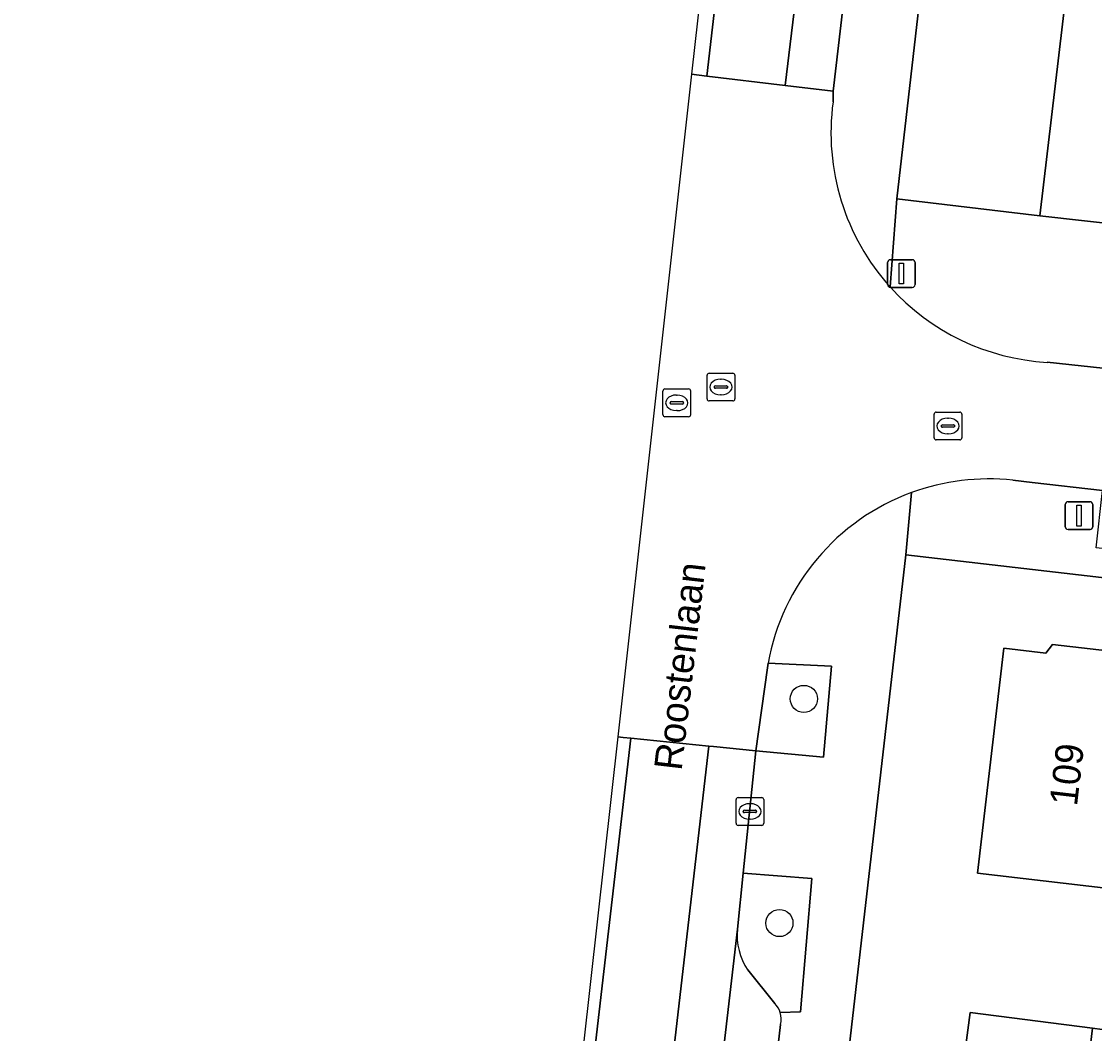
# Model space of a CAD drawing. Extents: x 162250 to 162661, y 380743 to 381606.
# Drawn here: x 162268.33 to 162306.99, y 381101.54 to 381138 of the extents above; entities that cross this region are included whole.
import ezdxf

# ---------------------------------------------------------------- set-up
doc = ezdxf.new("R2010")
doc.units = 0
for name, color, linetype in [('IMGEO_Boom', 7, 'Continuous'), ('IMGEO_Erf', 7, 'Continuous'), ('IMGEO_Kolk', 7, 'Continuous'), ('IMGEO_Lichtmast', 7, 'Continuous'), ('IMGEO_Openbare_ruimte_label', 7, 'Continuous'), ('IMGEO_Pand', 7, 'Continuous'), ('IMGEO_Pand_nummerreeks', 7, 'Continuous'), ('IMGEO_Parkeervlak_open', 7, 'Continuous'), ('IMGEO_Rijbaan_lokaal_gesloten', 7, 'Continuous'), ('IMGEO_Rioolput', 7, 'Continuous'), ('IMGEO_Verkeerseiland_groen', 7, 'Continuous'), ('IMGEO_Voetpad_open', 7, 'Continuous')]:
    doc.layers.add(name, color=color, linetype=linetype)

msp = doc.modelspace()

# ---------------------------------------------------------------- linework, layer by layer
at = {"layer": 'IMGEO_Boom'}
for centre in [(162296.514, 381113.595), (162295.634, 381105.521)]:
    msp.add_circle(centre, 0.489, dxfattribs=at)
at = {"layer": 'IMGEO_Erf'}
for points in [[(162341.565, 381113.994), (162300.19, 381118.786), (162298.069, 381100.412), (162302.196, 381099.936), (162302.502, 381102.301), (162306.912, 381101.731), (162307.261, 381101.686), (162311.531, 381101.218), (162316.15, 381100.712), (162320.788, 381100.203), (162320.754, 381099.942), (162320.583, 381098.618), (162322.993, 381098.336), (162323.098, 381101.264), (162325.575, 381101.155), (162325.478, 381098.962), (162329.957, 381098.765), (162334.625, 381098.559), (162334.521, 381096.197), (162340.767, 381095.921)], [(162312.118, 381106.22), (162307.503, 381106.762), (162302.77, 381107.317), (162303.72, 381115.418), (162305.233, 381115.24), (162305.471, 381115.559), (162308.494, 381115.204), (162311.273, 381114.878), (162311.568, 381114.505), (162313.07, 381114.329), (162317.684, 381113.787), (162322.299, 381113.246), (162326.914, 381112.705), (162328.309, 381112.541), (162328.707, 381112.855), (162331.571, 381112.519), (162334.469, 381112.179), (162334.767, 381111.802), (162336.266, 381111.626), (162335.313, 381103.499), (162330.578, 381104.055), (162325.963, 381104.596), (162321.348, 381105.137), (162316.733, 381105.679)]]:
    msp.add_lwpolyline(points, close=True, dxfattribs=at)
at = {"layer": 'IMGEO_Kolk'}
for p, q in [((162294.071, 381109.115), (162294.071, 381109.967)), ((162294.146, 381110.041), (162294.998, 381110.041)), ((162295.072, 381109.967), (162295.072, 381109.115)), ((162294.33, 381109.535), (162294.33, 381109.547)), ((162294.768, 381109.498), (162294.37, 381109.498)), ((162294.373, 381109.584), (162294.771, 381109.584)), ((162294.559, 381109.821), (162294.584, 381109.821)), ((162294.814, 381109.547), (162294.814, 381109.535)), ((162294.582, 381109.261), (162294.557, 381109.261)), ((162294.998, 381109.041), (162294.146, 381109.041))]:
    msp.add_line(p, q, dxfattribs=at)
for points in [[(162294.071, 381109.115), (162294.071, 381109.967)], [(162294.146, 381110.041), (162294.998, 381110.041)], [(162295.072, 381109.967), (162295.072, 381109.115)], [(162294.998, 381109.041), (162294.146, 381109.041)]]:
    msp.add_lwpolyline(points, dxfattribs=at)
for centre, radius, start, end in [((162294.148, 381109.965), 0.0765, 91.552, 178.448), ((162294.148, 381109.965), 0.0765, 91.552, 178.448), ((162294.996, 381109.965), 0.0765, 1.552, 88.448), ((162294.996, 381109.965), 0.0765, 1.552, 88.448), ((162294.37, 381109.544), 0.0403, 85.8775, 175.7526), ((162294.367, 381109.534), 0.0366, 178.938, 274.7102), ((162294.771, 381109.541), 0.043, 264.8664, 352.4533), ((162294.775, 381109.546), 0.0386, 1.7309, 96.639), ((162294.148, 381109.117), 0.0765, 181.552, 268.448), ((162294.148, 381109.117), 0.0765, 181.552, 268.448), ((162294.996, 381109.117), 0.0765, 271.552, 358.448), ((162294.996, 381109.117), 0.0765, 271.552, 358.448)]:
    msp.add_arc(centre, radius, start, end, dxfattribs=at)
for centre, major_axis, ratio, start_param, end_param in [((162294.558, 381109.541), (-0.387, 0.002), 0.722429, 4.712389, 7.853982), ((162294.583, 381109.541), (-0.39, 0.002), 0.717154, 1.570796, 4.712389)]:
    msp.add_ellipse(centre, major_axis=major_axis, ratio=ratio, start_param=start_param, end_param=end_param, dxfattribs=at)
at = {"layer": 'IMGEO_Lichtmast'}
for p, q in [((162299.532, 381128.517), (162299.532, 381129.317)), ((162299.532, 381129.317), (162299.532, 381128.517)), ((162299.632, 381129.417), (162300.422, 381129.417)), ((162300.422, 381129.417), (162299.632, 381129.417)), ((162300.522, 381129.317), (162300.522, 381128.517)), ((162300.522, 381128.517), (162300.522, 381129.317)), ((162300.422, 381128.417), (162299.632, 381128.417)), ((162299.632, 381128.417), (162300.422, 381128.417)), ((162306.034, 381120.698), (162306.824, 381120.698)), ((162306.824, 381120.698), (162306.034, 381120.698)), ((162305.934, 381119.798), (162305.934, 381120.598)), ((162305.934, 381120.598), (162305.934, 381119.798)), ((162306.924, 381120.598), (162306.924, 381119.798)), ((162306.924, 381119.798), (162306.924, 381120.598)), ((162306.824, 381119.698), (162306.034, 381119.698)), ((162306.034, 381119.698), (162306.824, 381119.698))]:
    msp.add_line(p, q, dxfattribs=at)
for points in [[(162299.952, 381129.292), (162300.102, 381129.292), (162300.102, 381128.542), (162299.952, 381128.542), (162299.952, 381129.292)], [(162306.354, 381120.573), (162306.504, 381120.573), (162306.504, 381119.823), (162306.354, 381119.823), (162306.354, 381120.573)]]:
    msp.add_lwpolyline(points, dxfattribs=at)
for centre, start, end in [((162299.632, 381129.317), 90, 180), ((162299.632, 381129.317), 90, 180), ((162300.422, 381129.317), 0, 90), ((162300.422, 381129.317), 360, 90), ((162299.632, 381128.517), 180, 270), ((162299.632, 381128.517), 180, 270), ((162300.422, 381128.517), 270, 0), ((162300.422, 381128.517), 270, 0), ((162306.034, 381120.598), 90, 180), ((162306.034, 381120.598), 90, 180), ((162306.824, 381120.598), 0, 90), ((162306.824, 381120.598), 360, 90), ((162306.034, 381119.798), 180, 270), ((162306.034, 381119.798), 180, 270), ((162306.824, 381119.798), 270, 0), ((162306.824, 381119.798), 270, 0)]:
    msp.add_arc(centre, 0.1, start, end, dxfattribs=at)
at = {"layer": 'IMGEO_Pand'}
for points in [[(162307.503, 381106.762), (162308.494, 381115.204), (162305.471, 381115.559), (162305.233, 381115.24), (162303.72, 381115.418), (162302.77, 381107.317)], [(162306.912, 381101.731), (162302.502, 381102.301), (162302.196, 381099.936), (162306.634, 381099.362), (162306.641, 381099.418)], [(162311.531, 381101.218), (162307.261, 381101.686), (162306.912, 381101.731), (162306.641, 381099.418), (162311.26, 381098.913), (162311.46, 381100.618), (162311.508, 381101.021)]]:
    msp.add_lwpolyline(points, close=True, dxfattribs=at)
at = {"layer": 'IMGEO_Parkeervlak_open'}
msp.add_lwpolyline([(162306.8, 381146.143), (162301.599, 381146.688), (162299.859, 381131.609), (162305.021, 381131.001)], close=True, dxfattribs=at)
for points in [[(162294.122, 381105.302), (162287.512, 381048.327)], [(162295.466, 381102.624), (162294.494, 381103.83)], [(162289.85, 381051.252), (162295.67, 381101.867)]]:
    msp.add_lwpolyline(points, dxfattribs=at)
for centre, radius, start, end in [((162296.342, 381105.08), 2.231, 174.2856, 214.0797), ((162294.924, 381102.07), 0.775, 17.0225, 45.6238), ((162294.973, 381102.074), 0.727, 343.4571, 17.8753)]:
    msp.add_arc(centre, radius, start, end, dxfattribs=at)
at = {"layer": 'IMGEO_Rijbaan_lokaal_gesloten'}
for points in [[(162292.47, 381136.097), (162293.013, 381136.032), (162294.312, 381147.256), (162293.722, 381147.326)], [(162297.201, 381146.915), (162294.312, 381147.256), (162293.013, 381136.032), (162295.844, 381135.69)], [(162298.875, 381146.718), (162297.201, 381146.915), (162295.844, 381135.69), (162297.571, 381135.481)], [(162274.657, 380977.597), (162274.701, 380977.591), (162290.278, 381112.181), (162290.005, 381112.208), (162289.809, 381112.228), (162286.357, 381081.269), (162276.732, 380995.981)], [(162294.788, 381111.726), (162293.261, 381111.88), (162293.089, 381111.897), (162278.556, 380986.022), (162277.507, 380977.016), (162279.203, 380976.84), (162279.928, 380983.133), (162281.338, 380995.138), (162281.526, 380996.953), (162287.288, 381046.38), (162287.512, 381048.327), (162294.122, 381105.302), (162294.331, 381107.316)]]:
    msp.add_lwpolyline(points, close=True, dxfattribs=at)
for points in [[(162297.568, 381135.102), (162297.571, 381135.481), (162295.844, 381135.69), (162293.013, 381136.032), (162292.47, 381136.097), (162291.049, 381123.351), (162289.809, 381112.228)], [(162304.043, 381121.471), (162304.742, 381121.392), (162307.271, 381121.104), (162307.344, 381121.095), (162307.851, 381125.447), (162307.735, 381125.461), (162305.277, 381125.719)], [(162289.809, 381112.228), (162290.005, 381112.208), (162290.278, 381112.181), (162293.089, 381111.897), (162293.261, 381111.88), (162294.788, 381111.726), (162295.203, 381114.719), (162295.216, 381114.798), (162295.23, 381114.877)], [(162268.325, 380921.495), (162271.149, 380921.172), (162275.659, 380960.888), (162277.356, 380960.724), (162278.069, 380966.836), (162278.655, 380972.068), (162279.19, 380976.722), (162279.196, 380976.775), (162279.203, 380976.84), (162277.507, 380977.016), (162278.556, 380986.022), (162293.089, 381111.897), (162290.278, 381112.181), (162274.701, 380977.591), (162274.657, 380977.597), (162268.325, 380921.495)]]:
    msp.add_lwpolyline(points, dxfattribs=at)
for centre, radius, start, end in [((162305.757, 381133.975), 8.266, 172.1638, 222.0719), ((162305.76, 381133.97), 8.266, 222.0345, 266.6486), ((162303.163, 381113.442), 8.077, 83.7481, 110.0612), ((162303.164, 381113.461), 8.06, 110.1109, 169.8797)]:
    msp.add_arc(centre, radius, start, end, dxfattribs=at)
at = {"layer": 'IMGEO_Rioolput'}
for p, q in [((162293.102, 381125.328), (162293.954, 381125.328)), ((162293.027, 381124.402), (162293.027, 381125.254)), ((162293.515, 381125.108), (162293.54, 381125.108)), ((162294.028, 381125.254), (162294.028, 381124.402)), ((162291.435, 381123.834), (162291.435, 381124.686)), ((162291.51, 381124.76), (162292.362, 381124.76)), ((162291.923, 381124.54), (162291.948, 381124.54)), ((162292.436, 381124.686), (162292.436, 381123.834)), ((162293.286, 381124.822), (162293.286, 381124.834)), ((162293.724, 381124.785), (162293.326, 381124.785)), ((162293.329, 381124.871), (162293.727, 381124.871)), ((162293.538, 381124.548), (162293.513, 381124.548)), ((162293.77, 381124.834), (162293.77, 381124.822)), ((162291.694, 381124.254), (162291.694, 381124.266)), ((162292.132, 381124.217), (162291.734, 381124.217)), ((162291.737, 381124.303), (162292.135, 381124.303)), ((162292.178, 381124.266), (162292.178, 381124.254)), ((162293.954, 381124.328), (162293.102, 381124.328)), ((162292.362, 381123.76), (162291.51, 381123.76)), ((162291.946, 381123.98), (162291.921, 381123.98)), ((162301.207, 381123), (162301.207, 381123.852)), ((162301.282, 381123.926), (162302.134, 381123.926)), ((162302.208, 381123.852), (162302.208, 381123)), ((162301.466, 381123.42), (162301.466, 381123.432)), ((162301.904, 381123.383), (162301.506, 381123.383)), ((162301.509, 381123.469), (162301.907, 381123.469)), ((162301.695, 381123.706), (162301.72, 381123.706)), ((162301.95, 381123.432), (162301.95, 381123.42)), ((162301.718, 381123.146), (162301.693, 381123.146)), ((162302.134, 381122.926), (162301.282, 381122.926))]:
    msp.add_line(p, q, dxfattribs=at)
for points in [[(162293.102, 381125.328), (162293.954, 381125.328)], [(162293.027, 381124.402), (162293.027, 381125.254)], [(162294.028, 381125.254), (162294.028, 381124.402)], [(162291.435, 381123.834), (162291.435, 381124.686)], [(162291.51, 381124.76), (162292.362, 381124.76)], [(162292.436, 381124.686), (162292.436, 381123.834)], [(162293.954, 381124.328), (162293.102, 381124.328)], [(162292.362, 381123.76), (162291.51, 381123.76)], [(162301.207, 381123), (162301.207, 381123.852)], [(162301.282, 381123.926), (162302.134, 381123.926)], [(162302.208, 381123.852), (162302.208, 381123)], [(162302.134, 381122.926), (162301.282, 381122.926)]]:
    msp.add_lwpolyline(points, dxfattribs=at)
for centre, radius, start, end in [((162293.104, 381125.252), 0.0765, 91.552, 178.448), ((162293.104, 381125.252), 0.0765, 91.552, 178.448), ((162293.952, 381125.252), 0.0765, 1.552, 88.448), ((162293.952, 381125.252), 0.0765, 1.552, 88.448), ((162291.512, 381124.684), 0.0765, 91.552, 178.448), ((162291.512, 381124.684), 0.0765, 91.552, 178.448), ((162292.36, 381124.684), 0.0765, 1.552, 88.448), ((162292.36, 381124.684), 0.0765, 1.552, 88.448), ((162293.326, 381124.831), 0.0403, 85.8775, 175.7526), ((162293.323, 381124.821), 0.0366, 178.938, 274.7102), ((162293.727, 381124.828), 0.043, 264.8664, 352.4533), ((162293.731, 381124.833), 0.0386, 1.7309, 96.639), ((162291.734, 381124.263), 0.0403, 85.8775, 175.7526), ((162291.731, 381124.253), 0.0366, 178.938, 274.7102), ((162292.135, 381124.26), 0.043, 264.8664, 352.4533), ((162292.139, 381124.265), 0.0386, 1.7309, 96.639), ((162293.104, 381124.404), 0.0765, 181.552, 268.448), ((162293.104, 381124.404), 0.0765, 181.552, 268.448), ((162293.952, 381124.404), 0.0765, 271.552, 358.448), ((162293.952, 381124.404), 0.0765, 271.552, 358.448), ((162291.512, 381123.836), 0.0765, 181.552, 268.448), ((162291.512, 381123.836), 0.0765, 181.552, 268.448), ((162292.36, 381123.836), 0.0765, 271.552, 358.448), ((162292.36, 381123.836), 0.0765, 271.552, 358.448), ((162301.284, 381123.85), 0.0765, 91.552, 178.448), ((162301.284, 381123.85), 0.0765, 91.552, 178.448), ((162302.132, 381123.85), 0.0765, 1.552, 88.448), ((162302.132, 381123.85), 0.0765, 1.552, 88.448), ((162301.506, 381123.429), 0.0403, 85.8775, 175.7526), ((162301.503, 381123.419), 0.0366, 178.938, 274.7102), ((162301.907, 381123.426), 0.043, 264.8664, 352.4533), ((162301.911, 381123.431), 0.0386, 1.7309, 96.639), ((162301.284, 381123.002), 0.0765, 181.552, 268.448), ((162301.284, 381123.002), 0.0765, 181.552, 268.448), ((162302.132, 381123.002), 0.0765, 271.552, 358.448), ((162302.132, 381123.002), 0.0765, 271.552, 358.448)]:
    msp.add_arc(centre, radius, start, end, dxfattribs=at)
for centre, major_axis, ratio, start_param, end_param in [((162293.514, 381124.828), (-0.387, 0.002), 0.722429, 4.712389, 7.853982), ((162293.539, 381124.828), (-0.39, 0.002), 0.717154, 1.570796, 4.712389), ((162291.922, 381124.26), (-0.387, 0.002), 0.722429, 4.712389, 7.853982), ((162291.947, 381124.26), (-0.39, 0.002), 0.717154, 1.570796, 4.712389), ((162301.694, 381123.426), (-0.387, 0.002), 0.722429, 4.712389, 7.853982), ((162301.719, 381123.426), (-0.39, 0.002), 0.717154, 1.570796, 4.712389)]:
    msp.add_ellipse(centre, major_axis=major_axis, ratio=ratio, start_param=start_param, end_param=end_param, dxfattribs=at)
at = {"layer": 'IMGEO_Verkeerseiland_groen'}
msp.add_lwpolyline([(162297.51, 381114.773), (162295.23, 381114.877), (162295.216, 381114.798), (162295.203, 381114.719), (162294.788, 381111.726), (162297.225, 381111.496)], close=True, dxfattribs=at)
for points in [[(162296.798, 381107.126), (162294.331, 381107.316), (162294.122, 381105.302)], [(162295.665, 381102.297), (162296.394, 381102.328), (162296.798, 381107.126)], [(162294.494, 381103.83), (162295.466, 381102.624)]]:
    msp.add_lwpolyline(points, dxfattribs=at)
for centre, radius, start, end in [((162296.342, 381105.08), 2.231, 174.2856, 214.0797), ((162294.924, 381102.07), 0.775, 17.0225, 45.6238)]:
    msp.add_arc(centre, radius, start, end, dxfattribs=at)
at = {"layer": 'IMGEO_Voetpad_open'}
for points in [[(162304.958, 381198.911), (162304.914, 381198.689), (162300.422, 381159.582), (162298.875, 381146.718), (162297.571, 381135.481), (162297.568, 381135.102)], [(162299.621, 381128.436), (162299.859, 381131.609), (162301.599, 381146.688), (162302.216, 381150.855), (162302.639, 381154.511), (162302.824, 381157.247), (162304.277, 381169.834), (162309.465, 381169.228), (162308.019, 381156.658), (162307.803, 381154.836), (162307.027, 381147.937), (162306.8, 381146.143), (162305.021, 381131.001), (162311.664, 381130.249), (162313.381, 381145.4), (162313.546, 381146.86), (162317.741, 381183.897)], [(162311.664, 381130.249), (162305.021, 381131.001), (162299.859, 381131.609), (162299.621, 381128.436)], [(162305.277, 381125.719), (162307.735, 381125.461), (162307.851, 381125.447), (162310.747, 381125.102), (162311.37, 381127.65), (162311.664, 381130.249)], [(162340.803, 381117.27), (162334.331, 381118.009), (162334.133, 381116.153), (162327.552, 381116.854), (162307.051, 381119.037), (162307.271, 381121.104), (162304.742, 381121.392), (162304.043, 381121.471)], [(162282.368, 380964.496), (162282.665, 380967.703), (162283.032, 380971.129), (162283.298, 380972.915), (162283.492, 380974.216), (162283.759, 380976.44), (162285.702, 380993.275), (162285.829, 380994.375), (162297.87, 381098.686), (162298.069, 381100.412), (162300.19, 381118.786), (162300.393, 381121.029)], [(162300.393, 381121.029), (162300.19, 381118.786), (162341.565, 381113.994), (162342.62, 381113.844), (162342.693, 381115.454), (162340.803, 381117.27)], [(162295.23, 381114.877), (162297.51, 381114.773), (162297.225, 381111.496), (162294.788, 381111.726), (162294.331, 381107.316), (162296.798, 381107.126), (162296.394, 381102.328), (162295.665, 381102.297)], [(162295.67, 381101.867), (162289.85, 381051.252)]]:
    msp.add_lwpolyline(points, dxfattribs=at)
for centre, radius, start, end in [((162305.757, 381133.975), 8.266, 172.1638, 222.0719), ((162305.76, 381133.97), 8.266, 222.0345, 266.6486), ((162303.163, 381113.442), 8.077, 83.7481, 110.0612), ((162303.164, 381113.461), 8.06, 110.1109, 169.8797), ((162294.973, 381102.074), 0.727, 343.4571, 17.8753)]:
    msp.add_arc(centre, radius, start, end, dxfattribs=at)

# ---------------------------------------------------------------- texts
at = {"layer": 'IMGEO_Openbare_ruimte_label'}
msp.add_text('Roostenlaan', height=1, rotation=83.337, dxfattribs=at).set_placement((162292.108, 381110.987))
at = {"layer": 'IMGEO_Pand_nummerreeks'}
msp.add_text('109', height=1, rotation=83.3115, dxfattribs=at).set_placement((162306.353, 381109.707))

doc.saveas('drawing.dxf')
